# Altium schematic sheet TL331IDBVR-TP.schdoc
size 127 x 101 mm
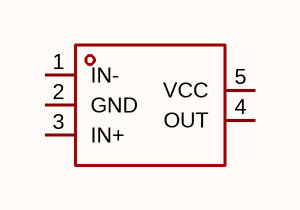
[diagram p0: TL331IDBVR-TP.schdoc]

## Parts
U?  tl331idbvr-tp  [TSOT-23-5_L2.9-W1.6-P0.95-LS2.8-BL]  (value not drawn)

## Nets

Not connected (* = marked no-connect by the designer): U? 1(IN-) 2(GND) 3(IN+) 4(OUT) 5(VCC)

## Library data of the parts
U? = tl331idbvr-tp: 比较器数:单路;输入失调电压(Vos):2mV;输入偏置电流(Ib):25nA;; Manufacturer: TECH PUBLIC(台舟); AddInBom: yes; ModelId: b5108020abe84f7bb0f3c398b43b6e0b; ModelName: TSOT-23-5_L2.9-W1.6-H1.00-LS2.8-P0.95; ModelTransform: 110.45568,114.173,0,90,0,0,0.0005,0,0; Number of Channels: 单路; Vos - Input Offset Voltage: 2mV; Ib - Input Bias Current: 25nA; Propagation Delay Time: 1.3us; Voltage - Supply: 2V~36V; Output Type: MOS；DTL；TTL；CMOS；ECL; Quiescent Current per Amplifier: 400uA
